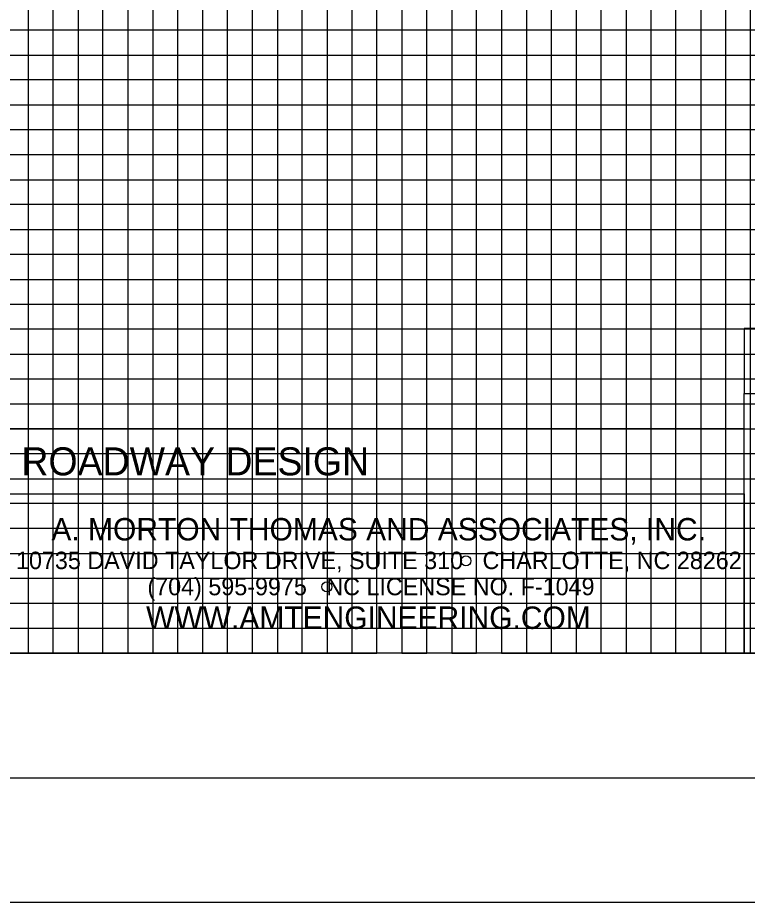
# Model space of a CAD drawing. Extents: x 1524869 to 1526553, y 501099 to 502199.
# Drawn here: x 1526289 to 1526435.4, y 501098.6 to 501276.1 of the extents above; entities that cross this region are included whole.
import ezdxf

# ---------------------------------------------------------------- set-up
doc = ezdxf.new("R2010")
doc.units = 0
for name, color, linetype in [('Prop Grid Mask', 7, 'Continuous'), ('Prop Horizontal Alignment Curve and Spiral Data', 7, 'Continuous'), ('Sheet Block Title CELL', 7, 'Continuous'), ('Sheet Layout Profile Border Port 2', 7, 'Continuous'), ('Sheet Plot Border Outside CELL', 7, 'Continuous'), ('Sheet Profile CELL', 7, 'Continuous'), ('Sheet Profile Grid Major CELL', 7, 'Continuous'), ('Sheet Profile Grid Middle CELL', 7, 'Continuous'), ('Sheet Profile Grid Minor CELL', 7, 'Continuous')]:
    doc.layers.add(name, color=color, linetype=linetype)

msp = doc.modelspace()

# ---------------------------------------------------------------- linework, layer by layer
at = {"layer": 'Prop Grid Mask'}
for points in [[(1526434.75, 501200.68), (1526536.08, 501200.68), (1526536.08, 501213.73), (1526434.75, 501213.73)], [(1526434.75, 501200.68), (1526536.08, 501200.68), (1526536.08, 501148.56), (1526434.75, 501148.56)], [(1526212.71, 501180.52), (1526434.75, 501180.52), (1526434.75, 501193.56), (1526212.71, 501193.56)], [(1526212.71, 501180.52), (1526434.75, 501180.52), (1526434.75, 501148.56), (1526212.71, 501148.56)]]:
    msp.add_lwpolyline(points, close=True, dxfattribs=at)
at = {"layer": 'Sheet Block Title CELL'}
msp.add_lwpolyline([(1526212.71, 501180.52), (1526434.75, 501180.52), (1526434.75, 501148.56), (1526212.71, 501148.56)], close=True, dxfattribs=at)
for centre in [(1526378.94, 501167.08), (1526351.02, 501161.86)]:
    msp.add_circle(centre, 1, dxfattribs=at)
at = {"layer": 'Sheet Layout Profile Border Port 2'}
msp.add_lwpolyline([(1525086.08, 501648.56), (1526486.08, 501648.56), (1526486.08, 501148.56), (1525086.08, 501148.56)], close=True, dxfattribs=at)
at = {"layer": 'Sheet Plot Border Outside CELL'}
msp.add_lwpolyline([(1524869.08, 501098.56), (1526553.08, 501098.56), (1526553.08, 502198.56), (1524869.08, 502198.56)], close=True, dxfattribs=at)
at = {"layer": 'Sheet Profile CELL'}
for p, q in [((1526536.08, 501148.56), (1525036.08, 501148.56)), ((1525036.08, 501123.56), (1526536.08, 501123.56))]:
    msp.add_line(p, q, dxfattribs=at)
msp.add_lwpolyline([(1526536.08, 502173.56), (1525036.08, 502173.56), (1525036.08, 501123.56), (1526536.08, 501123.56)], close=True, dxfattribs=at)
at = {"layer": 'Sheet Profile Grid Major CELL'}
for points in [[(1526086.08, 501148.56), (1526136.08, 501148.56), (1526136.08, 501648.56), (1526186.08, 501648.56), (1526186.08, 501148.56), (1526236.08, 501148.56), (1526236.08, 501648.56), (1526286.08, 501648.56), (1526286.08, 501148.56), (1526336.08, 501148.56), (1526336.08, 501648.56), (1526386.08, 501648.56), (1526386.08, 501148.56), (1526436.08, 501148.56), (1526436.08, 501148.56), (1526436.08, 501648.56), (1526486.08, 501648.56), (1526486.08, 501148.56)], [(1526536.08, 501248.56), (1525036.08, 501248.56), (1525036.08, 501248.56), (1525036.08, 501198.56), (1526536.08, 501198.56)], [(1526536.08, 501148.56), (1525036.08, 501148.56)]]:
    msp.add_lwpolyline(points, dxfattribs=at)
at = {"layer": 'Sheet Profile Grid Middle CELL'}
for points in [[(1526111.08, 501148.56), (1526161.08, 501148.56), (1526161.08, 501648.56), (1526211.08, 501648.56), (1526211.08, 501148.56), (1526261.08, 501148.56), (1526261.08, 501648.56), (1526311.08, 501648.56), (1526311.08, 501148.56), (1526361.08, 501148.56), (1526361.08, 501648.56), (1526411.08, 501648.56), (1526411.08, 501148.56), (1526461.08, 501148.56), (1526461.08, 501648.56)], [(1526536.08, 501273.56), (1525036.08, 501273.56), (1525036.08, 501223.56), (1526536.08, 501223.56)], [(1526536.08, 501173.56), (1525036.08, 501173.56)]]:
    msp.add_lwpolyline(points, dxfattribs=at)
at = {"layer": 'Sheet Profile Grid Minor CELL'}
for p, q in [((1525086.08, 501268.56), (1526486.08, 501268.56)), ((1526486.08, 501263.56), (1525086.08, 501263.56)), ((1525086.08, 501258.56), (1526486.08, 501258.56)), ((1526486.08, 501253.56), (1525086.08, 501253.56)), ((1525086.08, 501243.56), (1526486.08, 501243.56)), ((1526486.08, 501238.56), (1525086.08, 501238.56)), ((1525086.08, 501233.56), (1526486.08, 501233.56)), ((1526486.08, 501228.56), (1525086.08, 501228.56)), ((1525086.08, 501218.56), (1526486.08, 501218.56)), ((1526486.08, 501213.56), (1525086.08, 501213.56)), ((1525086.08, 501208.56), (1526486.08, 501208.56)), ((1526486.08, 501203.56), (1525086.08, 501203.56)), ((1525086.08, 501193.56), (1526486.08, 501193.56)), ((1526486.08, 501188.56), (1525086.08, 501188.56)), ((1525086.08, 501183.56), (1526486.08, 501183.56)), ((1526486.08, 501178.56), (1525086.08, 501178.56)), ((1525086.08, 501168.56), (1526486.08, 501168.56)), ((1526486.08, 501163.56), (1525086.08, 501163.56)), ((1525086.08, 501158.56), (1526486.08, 501158.56)), ((1525086.08, 501153.56), (1526486.08, 501153.56))]:
    msp.add_line(p, q, dxfattribs=at)
for points in [[(1526291.08, 501648.56), (1526291.08, 501148.56), (1526296.08, 501148.56), (1526296.08, 501648.56)], [(1526301.08, 501648.56), (1526301.08, 501148.56), (1526306.08, 501148.56), (1526306.08, 501648.56)], [(1526316.08, 501648.56), (1526316.08, 501148.56), (1526321.08, 501148.56), (1526321.08, 501648.56)], [(1526326.08, 501648.56), (1526326.08, 501148.56), (1526331.08, 501148.56), (1526331.08, 501648.56)], [(1526341.08, 501648.56), (1526341.08, 501148.56), (1526346.08, 501148.56), (1526346.08, 501648.56)], [(1526351.08, 501648.56), (1526351.08, 501148.56), (1526356.08, 501148.56), (1526356.08, 501648.56)], [(1526366.08, 501648.56), (1526366.08, 501148.56), (1526371.08, 501148.56), (1526371.08, 501648.56)], [(1526376.08, 501648.56), (1526376.08, 501148.56), (1526381.08, 501148.56), (1526381.08, 501648.56)], [(1526391.08, 501648.56), (1526391.08, 501148.56), (1526396.08, 501148.56), (1526396.08, 501648.56)], [(1526401.08, 501648.56), (1526401.08, 501148.56), (1526406.08, 501148.56), (1526406.08, 501648.56)], [(1526416.08, 501648.56), (1526416.08, 501148.56), (1526421.08, 501148.56), (1526421.08, 501648.56)], [(1526426.08, 501648.56), (1526426.08, 501148.56), (1526431.08, 501148.56), (1526431.08, 501648.56)]]:
    msp.add_lwpolyline(points, dxfattribs=at)

# ---------------------------------------------------------------- texts
at = {"layer": 'Prop Horizontal Alignment Curve and Spiral Data'}
msp.add_text('ROADWAY DESIGN', height=5.625, rotation=360, dxfattribs=at).set_placement((1526289.7, 501184.23))
at = {"layer": 'Sheet Block Title CELL'}
for s, height, p in [('A. MORTON THOMAS AND ASSOCIATES, INC.', 4.5, (1526295.72, 501171.17)), ('10735 DAVID TAYLOR DRIVE, SUITE 310   CHARLOTTE, NC 28262', 3.5, (1526288.62, 501165.42)), ('(704) 595-9975   NC LICENSE NO. F-1049', 3.5, (1526315, 501160.17)), ('WWW.AMTENGINEERING.COM', 4.5, (1526314.74, 501153.42))]:
    msp.add_text(s, height=height, rotation=359.9995, dxfattribs=at).set_placement(p)

doc.saveas('drawing.dxf')
